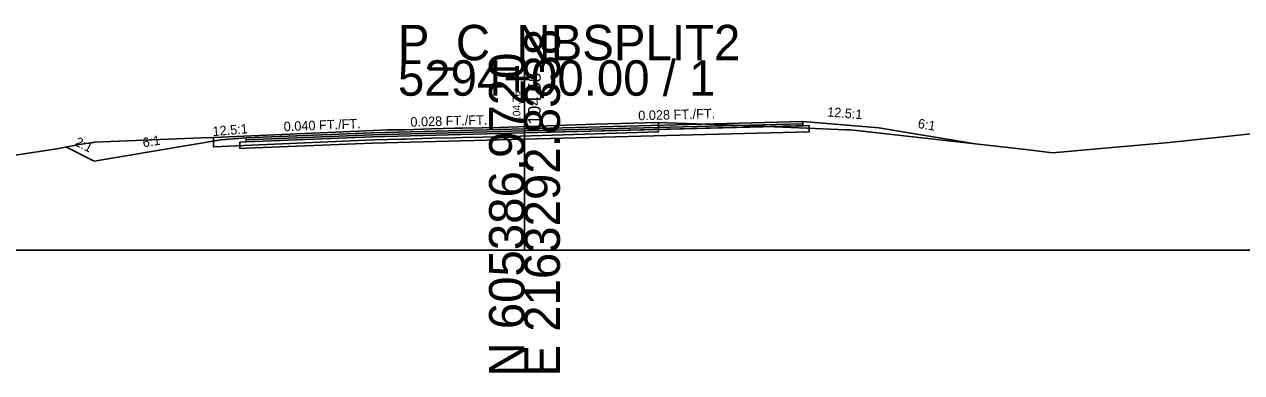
# Model space of a CAD drawing. Extents: x -26 to 1303, y -10 to 12038.
# Drawn here: x 110.5 to 206.7, y 7490.3 to 7517.8 of the extents above; entities that cross this region are included whole.
import ezdxf

# ---------------------------------------------------------------- set-up
doc = ezdxf.new("R2010")
doc.units = 0
for name, color, linetype in [('RD_GPK_XS_Cell', 7, 'Continuous'), ('RD_XS_Base', 7, 'Continuous'), ('RD_XS_ExGround', 7, 'Continuous'), ('RD_XS_ExPaveRet', 7, 'Continuous'), ('RD_XS_Greenside', 7, 'Continuous'), ('RD_XS_Pave', 7, 'Continuous'), ('RD_XS_PaveOvlay_CP', 7, 'Continuous'), ('RD_XS_TieSlope', 7, 'Continuous'), ('RD_XS_TX_Elev_EX', 7, 'Continuous'), ('RD_XS_TX_Elev_PR', 7, 'Continuous'), ('RD_XS_TX_ShdSlope', 7, 'Continuous'), ('RD_XS_TX_Slope', 7, 'Continuous')]:
    doc.layers.add(name, color=color, linetype=linetype)

msp = doc.modelspace()

# ---------------------------------------------------------------- linework, layer by layer
at = {"layer": 'RD_GPK_XS_Cell'}
for p, q in [((150, 7500), (150, 7515)), ((0, 7500), (150, 7500)), ((150, 7500), (300, 7500))]:
    msp.add_line(p, q, dxfattribs=at)
at = {"layer": 'RD_XS_Base'}
for p, q in [((150, 7509.258), (172.5, 7509.843)), ((172, 7509.83), (172, 7509.83)), ((172, 7509.83), (172, 7509.83)), ((172, 7509.83), (172, 7509.83)), ((172.5, 7509.843), (172.5, 7509.343)), ((172.5, 7509.81), (172.5, 7509.81)), ((128, 7508.546), (127.5, 7508.526)), ((127.5, 7508.526), (127.5, 7508.526)), ((127.5, 7508.526), (127.5, 7508.026)), ((138, 7508.946), (128, 7508.546)), ((128, 7508.546), (128, 7508.546)), ((150, 7509.258), (138, 7508.946)), ((138, 7508.946), (138, 7508.946)), ((138, 7508.446), (150, 7508.758)), ((150, 7508.758), (150, 7509.417)), ((150, 7509.417), (150, 7509.417)), ((150, 7509.417), (150, 7509.417)), ((150, 7509.417), (150, 7509.258)), ((172.5, 7509.343), (150, 7508.758)), ((150, 7509.258), (150, 7509.258)), ((150, 7508.758), (150, 7509.258)), ((150, 7509.258), (150, 7509.258)), ((150, 7509.258), (150, 7509.258)), ((150, 7508.758), (150, 7508.758)), ((172, 7509.33), (172, 7509.33)), ((172, 7509.33), (172, 7509.33)), ((127.5, 7508.026), (128, 7508.046)), ((128, 7508.046), (138, 7508.446)), ((128, 7508.046), (128, 7508.046)), ((138, 7508.446), (138, 7508.446))]:
    msp.add_line(p, q, dxfattribs=at)
at = {"layer": 'RD_XS_ExGround'}
msp.add_lwpolyline([(106.811, 7507.052), (113.057, 7508.011), (114.809, 7508.355), (115.918, 7508.514), (116.008, 7508.515), (124.485, 7508.866), (125.431, 7508.903), (138.078, 7509.449), (139.201, 7509.494), (140.247, 7509.506), (140.564, 7509.512), (142.639, 7509.592), (144.507, 7509.631), (145.073, 7509.646), (146.671, 7509.668), (148.006, 7509.693), (155.588, 7509.946), (160.58, 7510.089), (166.539, 7509.861), (172.979, 7509.6), (175.397, 7509.506), (175.761, 7509.498), (189.614, 7507.941), (191.712, 7507.675), (196.427, 7508.095), (200.934, 7508.498), (205.945, 7509.034), (209.004, 7509.358)], dxfattribs=at)
at = {"layer": 'RD_XS_ExPaveRet'}
for points in [[(155.588, 7509.946), (148.006, 7509.693), (148.006, 7509.693), (146.671, 7509.668), (146.671, 7509.668), (145.073, 7509.646), (145.073, 7509.646), (145.073, 7509.646), (144.507, 7509.631), (144.507, 7509.631), (142.639, 7509.592), (142.639, 7509.592), (140.564, 7509.512), (140.247, 7509.506), (140.247, 7509.506), (139.201, 7509.494), (139.201, 7509.494), (138.078, 7509.449), (138.078, 7509.449), (125.431, 7508.903), (125.431, 7508.903), (125.431, 7508.903), (125.431, 7508.153), (125.431, 7508.153), (125.431, 7508.153), (125.431, 7508.153), (138.078, 7508.699), (138.078, 7508.699), (139.201, 7508.744), (139.201, 7508.744), (140.247, 7508.756), (140.247, 7508.756), (140.564, 7508.762), (142.639, 7508.842), (142.639, 7508.842), (144.507, 7508.881), (144.507, 7508.881), (145.073, 7508.896), (145.073, 7508.896), (145.073, 7508.896), (146.671, 7508.918), (146.671, 7508.918), (148.006, 7508.943), (148.006, 7508.943), (155.588, 7509.196), (155.588, 7509.196), (160.58, 7509.339), (160.58, 7510.089), (160.58, 7510.089), (155.588, 7509.946), (155.588, 7509.946)], [(155.588, 7509.946), (148.006, 7509.693), (146.671, 7509.668), (145.073, 7509.646), (144.507, 7509.631), (142.639, 7509.592), (140.564, 7509.512), (140.247, 7509.506), (139.201, 7509.494), (138.078, 7509.449), (125.431, 7508.903), (125.431, 7508.903), (125.431, 7508.153), (125.431, 7508.153), (138.078, 7508.699), (139.201, 7508.744), (140.247, 7508.756), (140.564, 7508.762), (142.639, 7508.842), (144.507, 7508.881), (145.073, 7508.896), (146.671, 7508.918), (148.006, 7508.943), (155.588, 7509.196), (160.58, 7509.339), (160.58, 7510.089), (155.588, 7509.946)]]:
    msp.add_lwpolyline(points, dxfattribs=at)
at = {"layer": 'RD_XS_Greenside'}
for p, q in [((178, 7509.668), (185.771, 7508.373)), ((126, 7508.704), (116, 7507.037)), ((116, 7507.037), (113.772, 7508.151))]:
    msp.add_line(p, q, dxfattribs=at)
at = {"layer": 'RD_XS_Pave'}
for p, q in [((150, 7509.576), (138, 7509.264)), ((172, 7510.148), (150, 7509.576)), ((172, 7509.989), (150, 7509.417)), ((150, 7509.417), (172, 7509.989)), ((150, 7509.258), (172, 7509.83)), ((150, 7509.576), (150, 7509.576)), ((172, 7509.989), (172, 7510.148)), ((172, 7510.148), (172, 7510.148)), ((172, 7510.148), (172, 7510.148)), ((172, 7510.148), (172, 7510.148)), ((172, 7509.83), (172, 7509.989)), ((172, 7509.989), (172, 7509.989)), ((172, 7509.989), (172, 7509.989)), ((172, 7509.989), (172, 7509.989)), ((172, 7509.989), (172, 7509.989)), ((172, 7509.989), (172, 7509.989)), ((172, 7509.83), (172, 7509.83)), ((172, 7509.83), (172, 7509.83)), ((138, 7509.264), (128, 7508.864)), ((128, 7508.705), (138, 7509.105)), ((138, 7509.105), (128, 7508.705)), ((128, 7508.546), (138, 7508.946)), ((128, 7508.864), (128, 7508.864)), ((128, 7508.864), (128, 7508.705)), ((128, 7508.705), (128, 7508.705)), ((128, 7508.705), (128, 7508.546)), ((138, 7509.105), (150, 7509.417)), ((150, 7509.417), (138, 7509.105)), ((138, 7509.264), (138, 7509.264)), ((138, 7508.946), (150, 7509.258)), ((138, 7509.105), (138, 7509.105)), ((138, 7509.105), (138, 7509.105)), ((138, 7508.946), (138, 7508.946)), ((150, 7509.417), (150, 7509.417)), ((150, 7509.417), (150, 7509.417)), ((150, 7509.417), (150, 7509.258)), ((150, 7509.417), (150, 7509.417)), ((150, 7509.258), (150, 7509.417)), ((150, 7509.417), (150, 7509.417)), ((150, 7509.417), (150, 7509.417)), ((150, 7509.258), (150, 7509.258)), ((150, 7509.258), (150, 7509.258))]:
    msp.add_line(p, q, dxfattribs=at)
at = {"layer": 'RD_XS_PaveOvlay_CP'}
for p, q in [((150, 7509.576), (138, 7509.264)), ((172, 7510.148), (150, 7509.576)), ((150, 7509.576), (150, 7509.576)), ((172, 7510.148), (172, 7510.148)), ((172, 7510.148), (172, 7510.148)), ((138, 7509.264), (128, 7508.864)), ((138, 7509.264), (138, 7509.264))]:
    msp.add_line(p, q, dxfattribs=at)
at = {"layer": 'RD_XS_TieSlope'}
for p, q in [((172, 7510.148), (178, 7509.668)), ((128, 7508.864), (126, 7508.704))]:
    msp.add_line(p, q, dxfattribs=at)

# ---------------------------------------------------------------- texts
at = {"layer": 'RD_GPK_XS_Cell'}
for s, p in [('P_C_NBSPLIT2', (140, 7515)), ('5294+00.00 / 1', (140, 7512.2))]:
    msp.add_text(s, height=2.8, dxfattribs=at).set_placement(p)
for s, p in [('E 2163292.8338', (152.8, 7490)), ('N 605386.9720', (150, 7490))]:
    msp.add_text(s, height=2.8, rotation=90, dxfattribs=at).set_placement(p)
at = {"layer": 'RD_XS_TX_Elev_EX'}
msp.add_text('104.76', height=0.6, rotation=90, dxfattribs=at).set_placement((149.676, 7510.131))
at = {"layer": 'RD_XS_TX_Elev_PR'}
msp.add_text('104.58', height=1, rotation=90, dxfattribs=at).set_placement((151.281, 7509.917))
at = {"layer": 'RD_XS_TX_ShdSlope'}
for rotation, p in [(355.42608, (173.893, 7510.561)), (4.57392, (125.384, 7509.005))]:
    msp.add_text('12.5:1', height=0.75, rotation=rotation, dxfattribs=at).set_placement(p)
at = {"layer": 'RD_XS_TX_Slope'}
for s, rotation, p in [('0.028 FT./FT.', 1.60386, (140.999, 7509.751)), ('0.028 FT./FT.', 1.60386, (158.999, 7510.255)), ('0.040 FT./FT.', 2.29061, (130.995, 7509.387)), ('6:1', 350.53582, (181.034, 7509.656)), ('2:1', 333.43495, (114.396, 7508.306)), ('6:1', 9.46418, (119.893, 7508.108))]:
    msp.add_text(s, height=0.75, rotation=rotation, dxfattribs=at).set_placement(p)

doc.saveas('drawing.dxf')
